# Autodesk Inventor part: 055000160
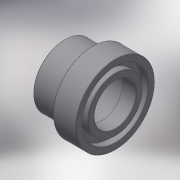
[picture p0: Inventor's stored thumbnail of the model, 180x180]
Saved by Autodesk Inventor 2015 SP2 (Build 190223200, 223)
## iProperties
Created: 2017-10
Part Number: 055000160
Material: Generic
Description: PLASSON FLANGE AD.+O-RING-CE 160
Document SubType Name: Modeling
Designer: KIM
Density: 1 g/cm^3
Appearance: Default
Author: KIM
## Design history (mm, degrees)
derived "055000.ipt"
feature "Solid1::055000.ipt"
tag "TaggingFeature1"
body "Solid1"
other parameters: "d0" = 98, "d1" = 185, "d3" = 144, "d4" = 19, "d5" = 86, "d6" = 213, "d8" = 5.7, "d11" = 1.6, "d12" = 5.7, "d15" = 10.35, "E_" = 185, "E_1" = 213, "l_" = 86, "B_" = 19, "H_" = 98, "d14" = 34.5
